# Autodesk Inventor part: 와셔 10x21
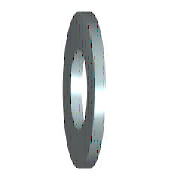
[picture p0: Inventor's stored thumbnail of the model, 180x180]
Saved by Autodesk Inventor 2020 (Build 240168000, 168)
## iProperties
Created: 2012-02
Part Number: 와셔 10x21
Material: 강철, 연강
Description: 평면 와셔
Document SubType Name: Modeling
Standard: KS B 1326
Designer: mduedu
Standards Organization: KS
Language: ko-KR
Size Designation: 10x21
Categories: <MemberInstance><Categories><Category DisplayName="조임쇠" InternalName="e4da775c-781d-43d5-af7c-5136215cf5a6" Mnemonic="FSTN"><Category DisplayName="와셔" InternalN
Density: 1 g/cm^3
Appearance: 파란색 - 벽 페인트 - 광택
IsCustomPart: 1
Author: mduedu
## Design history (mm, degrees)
sketch "스케치"
  geometry: C1 r 10.5 at (0, 0); C2 r 5.25 at (0, 0); 1 further point
  constraints: 2 centre point, 2 coincident
  dimensions: "d0" = 10.5 diameter of C2 (= SD1); "d1" = 21 diameter of C1 (= SD2)
extrude "본체" new body sketch "스케치" distance "d2" = 2 (= SD); taper "d3" = 0 deg
workaxis "Work Axis1"
workplane "Work Plane1"
body "Solid1"
other parameters: "SD1" = 10.5 [user parameter; used in 1 equation term], "SD2" = 21 [user parameter; used in 1 equation term], "SD" = 2 [user parameter; used in 1 equation term], "d4" = 0, "d5" = 0, "d6" = 0, "d7" = 0
